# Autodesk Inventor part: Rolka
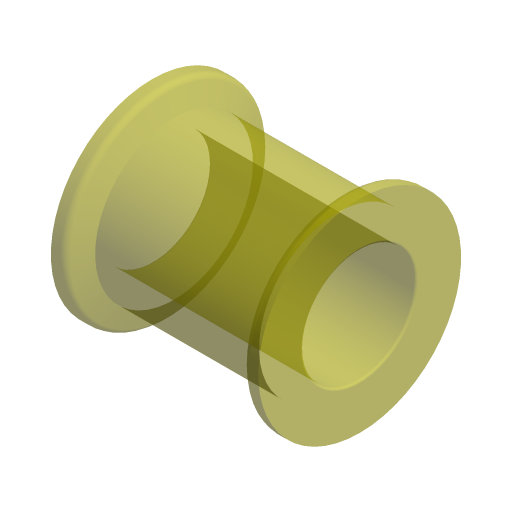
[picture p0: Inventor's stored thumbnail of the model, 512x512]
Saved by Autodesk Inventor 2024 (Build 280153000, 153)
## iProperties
Company: ATC
Shininess: 20.0
Length Units: 11269
Angle Units: 11279
Time Units: 11290
Mass Units: 11283
Length Display Precision: 3
Angle Display Precision: 2
Compacted: True
Created: 2023-03
Part Number: Rolka
Document SubType Name: Modeling
Designer: Andrzej Jaskulski
Material: Kurs-AJ
Density: 1 g/cm^3
Mass: 26.4779 g
Surface Area: 118.848 cm^2
Volume: 26.4779 cm^3
Appearance: Przezroczyste — żółte
Checked By: A.J.
Engr Approved By: Andrzej Jaskulski
Mfg Approved By: Andrzej Jaskulski
Authority: A.J.
Density: 0.0
Volumn: 0.0
Area: 0.0
PropertySet Name: Model Information
Control State: 0
Master: False
Checked Out: False
Title: A.J.: Kurs R2024-MEP
Author: Andrzej Jaskulski
Revision Number: 1/24
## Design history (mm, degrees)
node "Revolution1" dims "d7" = 90 deg
node "Fillet1" dims "d8" = 1.5
node "Fillet2" dims "d11" = 0.5
node "Bryła1"
node "Korpusy bryłowe"
node "Korpusy powierzchniowe"
sketch "Sketch1"
  geometry: L1 (20, -40)-(66, -40); L2 (66, -40)-(66, -30); L3 (66, -30)-(63, -30); L4 (63, -30)-(61.18, -35); L5 (61.18, -35)-(24.82, -35); L6 (24.82, -35)-(23, -30); L7 (23, -30)-(20, -30); L8 (20, -30)-(20, -40); L9 (14, -52.5)-(73, -52.5)
  constraints: 18 end point, 4 parallel, 3 equal length, 2 perpendicular, 1 horizontal, 1 other
  dimensions: "d0" = 10 distance of L1.end L2.end; "d1" = 5 distance between parallel lines of L1 L5; "d2" = 3 distance of L2.end L3.end; "d4" = 110 deg angle of L5 L4; "d5" = 46 distance of L2.end L7.end (derived); "d6" = 12.5 distance between parallel lines of L9 L1
